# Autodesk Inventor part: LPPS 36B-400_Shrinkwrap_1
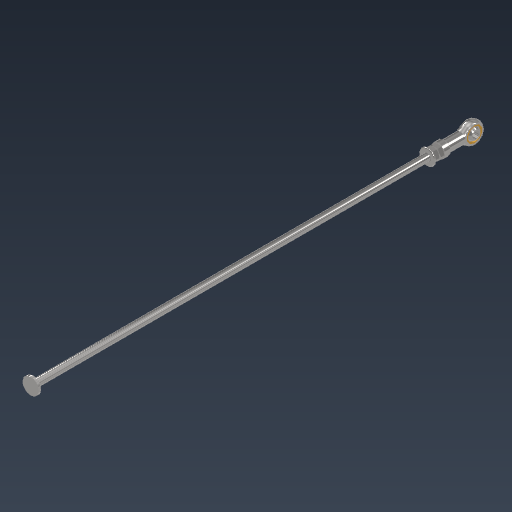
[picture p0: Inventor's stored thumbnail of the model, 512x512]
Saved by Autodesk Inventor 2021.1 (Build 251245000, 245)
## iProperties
Created: 2020-09
Part Number: LPPS 36B-400_Shrinkwrap_1
Material: Generic
Document SubType Name: Modeling
Designer: J. Nielson
Density: 1 g/cm^3
Appearance: Default
Author: J. Nielson
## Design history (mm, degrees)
derived "LPPS 36B-400.iam"
body "Solid1"
node "LPPS-36B-400 ROD.ipt:1"
node "Custom Flanged Nut.ipt:1"
body "Solid2"
node "FEMALE Rod End SW.ipt:1"
body "Solid3"
node "JIS B 1181 - M8x1(4).ipt:1"
body "Solid4"
